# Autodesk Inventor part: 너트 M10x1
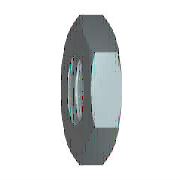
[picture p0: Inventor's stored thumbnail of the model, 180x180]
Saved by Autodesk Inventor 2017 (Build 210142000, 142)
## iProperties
Created: 2012-02
Part Number: 너트 M10x1
Material: 강철, 연강
Description: 6각 가는 너트 - 이중 모따기(부품 등급 A) - 정밀 나사산
Document SubType Name: Modeling
Standard: JIS B 1181
Designer: mduedu
Standards Organization: JIS
Language: ko-KR
Size Designation: M10x1
Categories: <MemberInstance><Categories><Category DisplayName="조임쇠" InternalName="e4da775c-781d-43d5-af7c-5136215cf5a6" Mnemonic="FSTN"><Category DisplayName="너트" InternalN
Density: 7.86 g/cm^3
Appearance: 강철
IsCustomPart: 1
Author: mduedu
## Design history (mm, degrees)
node "MSC_A1"
node "MSC_PT1"
node "MSC_PT2"
node "MSC_PF1"
body "Solid1"
sketch "스케치1"
  geometry: L1 (8, 4.619)-(8, -4.619); L2 (8, -4.619)-(0, -9.238); L3 (0, -9.238)-(-8, -4.619); L4 (-8, -4.619)-(-8, 4.619); L5 (-8, 4.619)-(0, 9.238); L6 (0, 9.238)-(8, 4.619); C1 r 8 at (0, 0); 2 further points
  constraints: 12 end point, 2 coincident, 1 centre point, 1 tangent, 1 vertical, 11 other
  dimensions: "d0" = 16 diameter of C1 (= ParS)
extrude "돌출1" new body sketch "스케치1" distance "d1" = 5 (= M); taper "d2" = 0 deg
sketch "스케치2"
  geometry: L1 (-8, 4.619)-(0, 9.238) reference; L2 (0, -9.238)-(-8, -4.619) reference; L3 (-8, 4.619)-(8, -4.619); L4 (-8, -4.619)-(8, 4.619); 1 further point
  constraints: 4 end point, 2 midpoint, 2 parallel
hole "구멍1" sketch "스케치2" diameter "d3" = 8.91747; stored, may be unused: countersink angle "d7" = 90 deg, drill point angle "d9" = 118 deg; dims "d4" = 6, "d5" = 4, "d6" = 2, "d8" = 8
chamfer "모따기1" distance "d10" = 0.5 (= 0.5 x PTC); stored, may be unused: second distance "d11" = 2, angle "d12" = 45 deg
revolve "회전1" stored, may be unused: angle "d15" = 90 deg
sketch "스케치3"
  geometry: L1 (-9.238, 5)-(-9.238, 4.285); L2 (-9.238, 4.285)-(-8, 5); L3 (-8, 5)-(-9.238, 5); L4 (-9.238, 0.715)-(-9.238, 0); L5 (-9.238, 0)-(-8, 0); L6 (-8, 0)-(-9.238, 0.715); L7 (0, 6)-(0, -1) reference; L8 (-4.619, 5)-(-9.238, 5) reference; L9 (-4.619, 0)-(-9.238, 0) reference; L10 (-9.238, 0)-(-9.238, 5) reference
  constraints: 12 end point, 4 collinear, 3 perpendicular, 2 equal length, 1 vertical
  dimensions: "d13" = 30 deg angle of L2 L3; "d14" = 8 distance from line of L2.end L7 (= 0.5 x ParS)
other parameters: "ParS" = 16 [user parameter; used in 2 equation terms], "M" = 5 [user parameter; used in 1 equation term], "PTC" = 1 [user parameter; used in 1 equation term], "d17" = 0, "d18" = 0, "d19" = 0, "d20" = 0, "d21" = 0, "d22" = 0, "d23" = 0
